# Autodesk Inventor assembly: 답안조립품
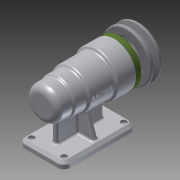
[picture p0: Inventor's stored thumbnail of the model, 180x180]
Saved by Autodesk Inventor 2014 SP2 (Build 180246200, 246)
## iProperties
Created: 2016-06
Part Number: 답안조립품
Document SubType Name: Assembly
Designer: 달님반
Author: 달님반
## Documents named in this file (12)
- C:\Users\달님반\Desktop\460607V1004\답안조립품.iam
- C:\Users\달님반\Desktop\460607V1004\V벨트풀리.ipt
- C:\Users\달님반\Desktop\460607V1004\멈춤나사 M3x8.ipt
- C:\Users\달님반\Desktop\460607V1004\베어링 6004.ipt
- C:\Users\달님반\Desktop\460607V1004\베어링 51202.ipt
- C:\Users\달님반\Desktop\460607V1004\본체.ipt
- C:\Users\달님반\Desktop\460607V1004\볼트 M4 x 12.ipt
- C:\Users\달님반\Desktop\460607V1004\어댑터슬리브.ipt
- C:\Users\달님반\Desktop\460607V1004\오일 실.ipt
- C:\Users\달님반\Desktop\460607V1004\축.ipt
- C:\Users\달님반\Desktop\460607V1004\커버.ipt
- C:\Users\달님반\Desktop\460607V1004\키 5 x 5 x 16.ipt
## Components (6 placed, 2 different names)
1. V벨트풀리:1
2. ISO 4762 M4 x 12:1
3. ISO 4762 M4 x 12:2
4. ISO 4762 M4 x 12:3
5. ISO 4762 M4 x 12:4
6. ISO 4762 M4 x 12:5
